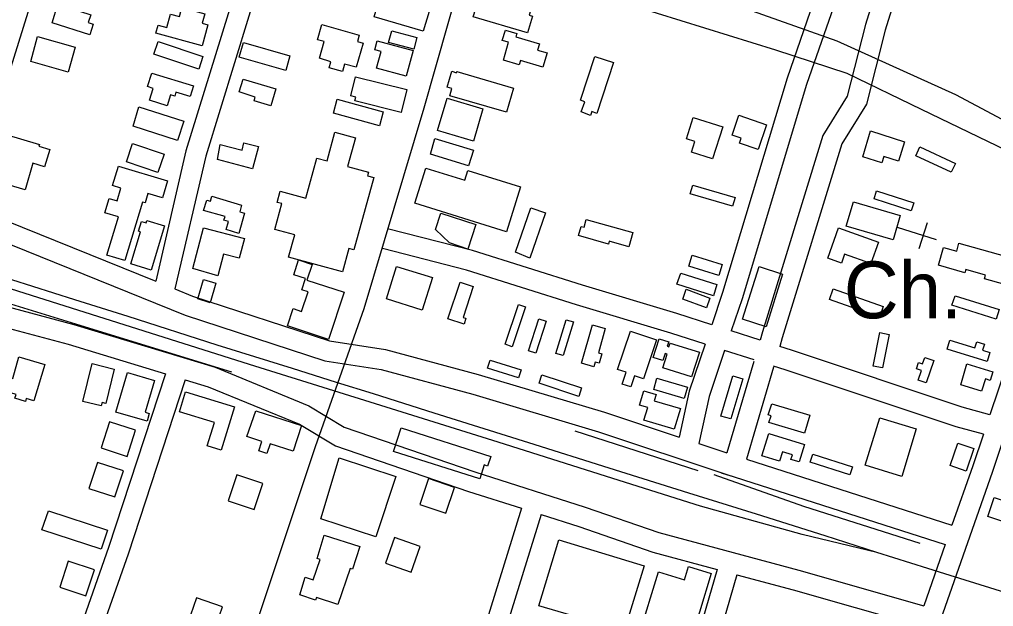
# Model space of a CAD drawing. Extents: x 3324125 to 3362000, y 600753 to 626151.
# Drawn here: x 3339347 to 3340770, y 607022 to 607880 of the extents above; entities that cross this region are included whole.
import ezdxf

# ---------------------------------------------------------------- set-up
doc = ezdxf.new("R2010")
doc.units = 0
for name, color, linetype in [('V-BLDG-OTLN', 7, 'Continuous'), ('V-RAIL-TRAK', 7, 'Continuous'), ('V-ROAD-CNTR', 7, 'Continuous'), ('V-SITE-OTLN', 7, 'Continuous'), ('V-SITE-OTLN-IDEN', 7, 'Continuous'), ('V-TOPO-SHOR', 7, 'Continuous')]:
    doc.layers.add(name, color=color, linetype=linetype)

msp = doc.modelspace()

# ---------------------------------------------------------------- linework, layer by layer
at = {"layer": 'V-BLDG-OTLN'}
for points in [[(3340021.5, 607919.4), (3340095.5, 607897.4), (3340092.1, 607886), (3340096.8, 607884.5), (3340089.5, 607860.1), (3340010.3, 607883.7)], [(3339395.3, 607874.7), (3339403.2, 607901.9), (3339451.6, 607886.6), (3339447.9, 607875.1), (3339455.2, 607872.8), (3339450.3, 607857.3)], [(3339874, 607912.4), (3339945.6, 607891.4), (3339937.1, 607862.7), (3339865.6, 607883.8)], [(3339546.5, 607859.7), (3339549.9, 607871.2), (3339562.6, 607867.8), (3339568, 607887.5), (3339580.9, 607884), (3339584.6, 607897.3), (3339618.1, 607888.1), (3339614.4, 607874.4), (3339622.6, 607872.1), (3339614.2, 607841.3)], [(3339785.4, 607823.1), (3339792.3, 607847.5), (3339782.6, 607850.2), (3339788.8, 607872.5), (3339843.8, 607857), (3339841.1, 607847.4), (3339849.2, 607845.2), (3339839.2, 607809.9), (3339822.3, 607814.6), (3339819.3, 607803.8), (3339799.9, 607809.2), (3339802.3, 607817.9)], [(3339886.6, 607846.3), (3339891.4, 607863.1), (3339927.9, 607853.5), (3339923.4, 607836.5)], [(3340054.5, 607820.4), (3340061.6, 607846.5), (3340052.6, 607849.1), (3340057.1, 607864.3), (3340073.8, 607859.3), (3340072.3, 607854.5), (3340106.8, 607844.1), (3340104.1, 607835.1), (3340118.2, 607830.9), (3340111.9, 607809.9), (3340079.3, 607819.6), (3340077.5, 607813.6)], [(3339364.1, 607818.2), (3339373.9, 607854.9), (3339428.9, 607839.2), (3339418.4, 607802.6)], [(3339609.2, 607807.1), (3339543.6, 607829.1), (3339549.8, 607847.4), (3339615, 607825.5)], [(3339742.5, 607826.5), (3339736.3, 607805.1), (3339668.3, 607824.8), (3339674.5, 607846.2)], [(3339869, 607808.4), (3339875.6, 607833.1), (3339866.4, 607835.6), (3339869.9, 607848.7), (3339922.5, 607834.6), (3339912.4, 607796.8)], [(3340190.9, 607742.1), (3340183.6, 607745.3), (3340181.3, 607739.5), (3340167.9, 607745), (3340173.3, 607759.2), (3340166.7, 607761.8), (3340187.9, 607825.6), (3340215.1, 607816.8)], [(3340069.2, 607779.3), (3340058.9, 607744.3), (3339976.1, 607768.4), (3339979.1, 607778.7), (3339972.1, 607780.8), (3339978.8, 607804), (3339985.7, 607802), (3339986.1, 607803.5)], [(3339540.8, 607801.1), (3339601.6, 607782.6), (3339596.9, 607767.1), (3339575.7, 607773.5), (3339574.1, 607767.9), (3339568, 607769.7), (3339563.2, 607753.7), (3339537.3, 607761.6), (3339542.6, 607779.1), (3339534.4, 607781.6)], [(3339674.1, 607792.3), (3339721.8, 607778.2), (3339714.6, 607753.7), (3339690.2, 607760.9), (3339691.8, 607766.2), (3339668.2, 607773.8)], [(3339904.7, 607743.9), (3339837.1, 607760.7), (3339838.5, 607766.3), (3339831.2, 607768.1), (3339838.1, 607796), (3339913, 607777.5)], [(3339805.9, 607742.8), (3339811.5, 607763.2), (3339878.7, 607744.7), (3339873.1, 607724.3)], [(3339957.9, 607717.5), (3339972.1, 607764.8), (3340024.4, 607749.3), (3340010.4, 607702)], [(3339521.6, 607752.2), (3339587.2, 607731.3), (3339578.1, 607702.9), (3339513.2, 607723.7)], [(3340374.6, 607723), (3340359.5, 607675.9), (3340329, 607685.6), (3340334.1, 607701.4), (3340321.6, 607705.4), (3340331.6, 607736.7)], [(3340438.7, 607726), (3340426.4, 607689.6), (3340399.1, 607698.8), (3340401.6, 607706.2), (3340388.4, 607710.7), (3340398.2, 607739.7)], [(3340579.5, 607679), (3340590.4, 607716.8), (3340640.3, 607700.9), (3340631.4, 607672.8), (3340609.8, 607679.6), (3340606.9, 607670.4)], [(3339355.8, 607630.6), (3339322.6, 607640.7), (3339321.6, 607637.4), (3339304.8, 607642.5), (3339326, 607712.2), (3339376.4, 607696.8), (3339375.7, 607694.6), (3339391.8, 607689.7), (3339384.1, 607664.6), (3339366.8, 607669.9)], [(3339740.5, 607532.5), (3339749.4, 607565), (3339720.2, 607573), (3339730.5, 607610.6), (3339723.7, 607612.5), (3339728.2, 607628.8), (3339765.7, 607618.5), (3339781.8, 607677.3), (3339796.7, 607673.2), (3339808.2, 607715), (3339838.1, 607706.8), (3339826.7, 607665.1), (3339857.2, 607656.7), (3339855.7, 607651.4), (3339865, 607648.8), (3339836, 607543.1), (3339828.4, 607545.2), (3339819, 607511)], [(3339947.8, 607682.9), (3339954.3, 607705.8), (3340010.5, 607688.7), (3340003.5, 607665.9)], [(3339503.5, 607671.7), (3339512.6, 607698.6), (3339558.6, 607683), (3339549.5, 607656.2)], [(3339636.5, 607674.9), (3339640.6, 607697.2), (3339672.5, 607688.9), (3339675.3, 607699.5), (3339696.3, 607694), (3339687.8, 607661.6)], [(3340656.7, 607680.7), (3340662.6, 607693.8), (3340714.6, 607669.4), (3340708.5, 607656.4)], [(3339491.9, 607665.5), (3339563.7, 607643.8), (3339556.2, 607619), (3339535, 607625.4), (3339530.9, 607611.8), (3339527.2, 607612.9), (3339501.4, 607527.4), (3339474.9, 607535.4), (3339491.8, 607591.5), (3339472, 607597.4), (3339478.3, 607618.1), (3339490, 607614.6), (3339495.6, 607633.2), (3339483.4, 607636.9)], [(3339925, 607611.1), (3339941.2, 607662.5), (3339997.9, 607644.9), (3340002.3, 607659.1), (3340079.1, 607635.2), (3340058.7, 607569.5)], [(3340327.1, 607624.9), (3340330.9, 607637.4), (3340392.7, 607619.4), (3340389.1, 607606.8)], [(3339649.1, 607572.6), (3339652.8, 607584.7), (3339646.1, 607586.6), (3339647.6, 607591.6), (3339616.4, 607600.7), (3339620.9, 607615.9), (3339626.5, 607614.3), (3339628.5, 607621.3), (3339671.9, 607608.6), (3339669, 607598.6), (3339676.2, 607596.5), (3339667.6, 607567.2)], [(3340595.7, 607617.5), (3340599.3, 607629.3), (3340653.7, 607611.9), (3340650, 607600.2)], [(3340071.8, 607539.6), (3340094.2, 607604.5), (3340115.7, 607597), (3340092.9, 607531.1)], [(3340555, 607577.8), (3340565.9, 607613.2), (3340633.8, 607593.5), (3340623.5, 607557.9)], [(3340013.9, 607580), (3340002.3, 607544.3), (3339975.3, 607553.1), (3339955.2, 607572.8), (3339962.9, 607596.5)], [(3339510.1, 607522.4), (3339524.3, 607569.3), (3339521.4, 607570.2), (3339525.8, 607584.7), (3339532.4, 607582.7), (3339533.4, 607586), (3339559.4, 607578.1), (3339539.6, 607513.4)], [(3339600.8, 607515.7), (3339616.3, 607575.1), (3339676, 607559.5), (3339668.5, 607530.8), (3339645.6, 607536.8), (3339637.3, 607505.1)], [(3340175.1, 607587.5), (3340243.2, 607568.4), (3340237.4, 607547.6), (3340209, 607555.6), (3340207.9, 607551.6), (3340164.1, 607563.9), (3340167.8, 607577.4), (3340172.5, 607576.1)], [(3340543.7, 607575.2), (3340602, 607554.5), (3340590.9, 607523.2), (3340552.6, 607536.8), (3340548, 607523.8), (3340528.4, 607530.7)], [(3340689.9, 607520.5), (3340697.1, 607546.4), (3340716.5, 607541), (3340719.8, 607552.6), (3340798, 607530.7), (3340796.4, 607525.1), (3340801, 607523.8), (3340793.6, 607497.4), (3340788.5, 607498.8), (3340786.7, 607492.4), (3340757.2, 607500.7), (3340758.7, 607506.2), (3340729.8, 607514.3), (3340728.5, 607509.7)], [(3340325.2, 607519.3), (3340329.9, 607535.4), (3340373.9, 607521.5), (3340368.9, 607505.5)], [(3339739, 607431.9), (3339747.3, 607457.2), (3339759.4, 607453.2), (3339768.9, 607481.7), (3339759.8, 607484.7), (3339765.2, 607501.1), (3339748, 607506.8), (3339755.1, 607528.4), (3339774.7, 607521.9), (3339767.1, 607499), (3339821.6, 607481), (3339798.8, 607412.1)], [(3339883.6, 607471.3), (3339898.1, 607518.9), (3339950.5, 607502.6), (3339935.7, 607455.1)], [(3340403.4, 607441.6), (3340427.7, 607518.5), (3340462.2, 607507.6), (3340437.9, 607430.7)], [(3340307.8, 607492.7), (3340313.7, 607509.2), (3340366.3, 607492.4), (3340361, 607475.7)], [(3339608.1, 607471.7), (3339616.4, 607499.7), (3339634.2, 607494.5), (3339625.7, 607465.6)], [(3339990.9, 607495.6), (3340009.9, 607489.4), (3339995.3, 607444.4), (3339999.6, 607443), (3339996.9, 607434.7), (3339973.2, 607442.4)], [(3340316.5, 607471.2), (3340321.4, 607485.4), (3340356, 607472.7), (3340350.8, 607458.5)], [(3340530.5, 607470.6), (3340535.9, 607486), (3340609.1, 607460.3), (3340603.7, 607444.9)], [(3340709.6, 607462.3), (3340714.1, 607475.9), (3340778.4, 607455.7), (3340774.1, 607442)], [(3340057, 607405.1), (3340076.2, 607463), (3340086.4, 607459.6), (3340067.1, 607401.5)], [(3340090.9, 607395.7), (3340106.1, 607442.3), (3340116.8, 607438.8), (3340101.6, 607392.1)], [(3340131, 607391.8), (3340145.8, 607441), (3340156.5, 607437.7), (3340141.7, 607388.5)], [(3340168.5, 607377.3), (3340184.4, 607433.4), (3340203.1, 607428.2), (3340193, 607392.7), (3340198.1, 607391.3), (3340194.1, 607377.3), (3340188.3, 607379), (3340186.4, 607372.2)], [(3340277.8, 607411.8), (3340258.9, 607354.6), (3340245.6, 607359), (3340240.2, 607342.8), (3340227.7, 607346.9), (3340233.5, 607364.1), (3340221.1, 607368.2), (3340239.8, 607424.4)], [(3340594.4, 607373.1), (3340604.1, 607422.1), (3340617.8, 607419.4), (3340608.2, 607370.4)], [(3340340.5, 607393.4), (3340329.2, 607357.6), (3340287.3, 607370.5), (3340293.4, 607390.6), (3340290.6, 607391.4), (3340287.4, 607381.2), (3340273.2, 607385.7), (3340281.9, 607413.2), (3340295.8, 607408.8), (3340293.7, 607402.1), (3340296, 607401.4), (3340297.7, 607406.9)], [(3340760.8, 607379.7), (3340702.5, 607397.8), (3340706.6, 607411.1), (3340743.2, 607399.7), (3340745.9, 607408.4), (3340757, 607405), (3340754.4, 607396.5), (3340764.9, 607393.2)], [(3339346.4, 607386.8), (3339384.3, 607375.3), (3339368.2, 607322.6), (3339357.3, 607325.9), (3339355.9, 607321.4), (3339340.6, 607326.1), (3339342.4, 607331.6), (3339320.6, 607338.3), (3339326.7, 607358.5), (3339337.6, 607355.2)], [(3339453.5, 607376.9), (3339485.9, 607368.9), (3339473.6, 607318.7), (3339468.1, 607320), (3339466.9, 607314.9), (3339439.8, 607321.5)], [(3340030.9, 607370.1), (3340035, 607381.7), (3340080.1, 607367.7), (3340076.5, 607356)], [(3340672, 607348.6), (3340660.4, 607352.6), (3340665.2, 607366.7), (3340657.6, 607369.3), (3340660.7, 607378.3), (3340666.7, 607376.3), (3340670, 607385.8), (3340683.2, 607381.3)], [(3340722.3, 607345.8), (3340731.5, 607376.6), (3340769.4, 607365), (3340765.5, 607352.3), (3340758.4, 607354.4), (3340752.9, 607336.4)], [(3339544.6, 607352.3), (3339530.8, 607305.7), (3339537, 607303.8), (3339533.7, 607292.5), (3339488.2, 607305.9), (3339505.3, 607363.9)], [(3340106.7, 607348), (3340110.3, 607360.5), (3340168.4, 607341.2), (3340164.3, 607328.8)], [(3340274, 607339), (3340278.5, 607355.4), (3340323.3, 607342.3), (3340318.5, 607326)], [(3340371.7, 607300.2), (3340389.4, 607358.9), (3340404, 607354.5), (3340386.3, 607296.1)], [(3339589.7, 607335.7), (3339661.5, 607313.6), (3339642.1, 607250.5), (3339621.6, 607256.8), (3339632.1, 607290.9), (3339581.2, 607306.5)], [(3340259.6, 607294.1), (3340265.4, 607312.5), (3340253, 607316.2), (3340259.4, 607337.2), (3340277.2, 607331.8), (3340274.4, 607322.6), (3340312.8, 607311), (3340303.7, 607280.8)], [(3340446.3, 607317.9), (3340501.7, 607301.6), (3340494, 607275.4), (3340442.2, 607290.6), (3340445.2, 607300.7), (3340441.2, 607301.8)], [(3339692.5, 607307.8), (3339759.2, 607286.5), (3339747.2, 607249), (3339713.4, 607259.8), (3339708.8, 607245.4), (3339697.1, 607249.1), (3339701.6, 607263.2), (3339679.5, 607270.3)], [(3339504.5, 607241.3), (3339516.9, 607279.3), (3339478.9, 607291.8), (3339466.5, 607253.7)], [(3340582.7, 607228.6), (3340604, 607297.8), (3340657.5, 607281.4), (3340636.1, 607211.9)], [(3339904.9, 607282.8), (3340035.7, 607241.2), (3340031.2, 607227.1), (3340026.3, 607228.7), (3340019.9, 607208.3), (3339893.8, 607248.4)], [(3340431.9, 607242.1), (3340441.8, 607274.5), (3340494, 607258.5), (3340486.2, 607233.3), (3340474.3, 607236.9), (3340476.4, 607243.6), (3340462.1, 607248), (3340457.8, 607234.1)], [(3340706.9, 607227.8), (3340718.1, 607260.6), (3340741.5, 607252.6), (3340730.2, 607219.4)], [(3339486.8, 607182), (3339499.2, 607220), (3339461.2, 607232.4), (3339448.7, 607194.4)], [(3339787.5, 607150.1), (3339814.4, 607239.1), (3339897.2, 607211.8), (3339868, 607123.5)], [(3340502.6, 607232.8), (3340506.5, 607244.5), (3340564.3, 607226.1), (3340560.5, 607214.3)], [(3339690, 607163.6), (3339702.8, 607201.5), (3339664.9, 607214.3), (3339652.1, 607176.4)], [(3339982.8, 607195.9), (3339944.9, 607208.7), (3339932.1, 607170.8), (3339970, 607158)], [(3340887.3, 607142.3), (3340878.3, 607114.6), (3340842.5, 607126.6), (3340844.2, 607131.5), (3340820.8, 607139.3), (3340819.1, 607134.3), (3340761.9, 607153.4), (3340771.2, 607181.1)], [(3339389.7, 607161.6), (3339475.7, 607133.5), (3339466.6, 607105.7), (3339379.8, 607134)], [(3339756.9, 607038.8), (3339764.8, 607064.6), (3339776.5, 607060.7), (3339786.6, 607090.6), (3339782.1, 607092.1), (3339792.4, 607126.1), (3339844.3, 607109.6), (3339833.9, 607076.4), (3339830.3, 607077.6), (3339812.4, 607024.6), (3339781.4, 607035), (3339780, 607031.1)], [(3339932.8, 607109.6), (3339895.1, 607122.8), (3339881.8, 607085.1), (3339919.6, 607071.9)], [(3340106, 607022.9), (3340135.2, 607119.2), (3340259.8, 607081.5), (3340230.9, 606986.2)], [(3339444.3, 607037.5), (3339456.7, 607075.5), (3339418.7, 607087.9), (3339406.2, 607049.9)], [(3340252.3, 606978.8), (3340280.9, 607072.4), (3340318.8, 607060.8), (3340324.7, 607080.1), (3340358, 607069.9), (3340323.6, 606957.2)], [(3339630.9, 606983.5), (3339643.7, 607021.4), (3339605.8, 607034.3), (3339593, 606996.4)]]:
    msp.add_lwpolyline(points, close=True, dxfattribs=at)
at = {"layer": 'V-RAIL-TRAK'}
for points in [[(3340342.3, 607168.5), (3340214.1, 607208.9), (3340046.4, 607261.8), (3339867.5, 607318.1), (3339806.6, 607337.1), (3339683.6, 607375.3), (3339452.7, 607448.4), (3339256.9, 607510.3), (3339233.1, 607517.7), (3339114.4, 607556), (3338941.5, 607610.2), (3338770.8, 607663.9), (3338616.1, 607712.1), (3338384, 607785.4), (3338129, 607865.5)], [(3339506.3, 607445.6), (3339428.3, 607470.1), (3339274.1, 607518.6), (3339236.7, 607530.7), (3339161.8, 607554.3), (3339037, 607593.5), (3338878, 607643.8), (3338754.5, 607682.4), (3338609, 607728.9), (3338482, 607768.4), (3338335.2, 607815.3), (3338181, 607863.9)], [(3340816.5, 607032.9), (3340699, 607069.6), (3340599.6, 607100.7), (3340524.1, 607124.9), (3340424, 607156.7), (3340325.2, 607187.7), (3340208.7, 607224), (3340091.3, 607261.2), (3339953.1, 607304.3), (3339864.7, 607332.5), (3339810.5, 607349.4), (3339746.4, 607369.6), (3339636, 607403.9), (3339506.3, 607445.6)], [(3340599.6, 607100.7), (3340490.5, 607127.3), (3340342.3, 607168.5)]]:
    msp.add_lwpolyline(points, dxfattribs=at)
at = {"layer": 'V-ROAD-CNTR'}
for points in [[(3339883.1, 608748.6), (3339846.5, 608600.3), (3339828.2, 608538.2), (3339723.8, 608153.1), (3339695.5, 608029), (3339590.4, 607687.6), (3339546.3, 607497.3)], [(3339912.3, 608741.4), (3339875.5, 608592.5), (3339857.1, 608530), (3339752.9, 608145.9), (3339724.5, 608021.3), (3339619.4, 607679.8), (3339574.4, 607486)], [(3339271.1, 607605), (3339277.6, 607627.6), (3339428, 608110), (3339471.4, 608240.6), (3339580.5, 608609.5), (3339593.8, 608640.1)], [(3340880.6, 608635), (3340915.1, 608606.2), (3341166.1, 608521.9), (3340907.9, 607736), (3340856.4, 607573.3), (3340765.1, 607302.1)], [(3340836.6, 608614.5), (3340830.2, 608575.2), (3340725.1, 608227), (3340612.2, 607864.2), (3340584.7, 607755.8), (3340548.5, 607697.8), (3340461.7, 607414.7), (3340457.9, 607402)], [(3339432.1, 606157.1), (3339565.6, 606591.7), (3339595.2, 606701.5), (3339779.9, 607255.8), (3339850.8, 607457.2), (3339938.7, 607750.4), (3339991.4, 607937.6), (3340033.3, 608065.6), (3340109.3, 608306.5), (3340151.5, 608473.1)], [(3338095.1, 608382.4), (3338259.1, 608370.6), (3338551.7, 608360.9), (3338678.9, 608355.4), (3338759.9, 608349.8), (3338867.9, 608336.9), (3338938.4, 608324.4), (3339016.8, 608313.1), (3339101, 608289.9), (3339704.4, 608109), (3340246.4, 607951.2), (3340394.5, 607900.5), (3340541.5, 607848.4), (3340714.9, 607769.9), (3340880.1, 607681.8)], [(3338030.8, 608297.2), (3338260.6, 608280.3), (3338440.8, 608273.8), (3338606.7, 608268.3), (3338780.2, 608265.1), (3338943.4, 608261), (3339024.4, 608253.5), (3339134, 608234.5), (3339262.6, 608211.2), (3339404.8, 608161.6), (3340039.2, 607964.4), (3340279.1, 607888.9), (3340451.7, 607835.6), (3340556, 607801.3), (3340664.6, 607748.6), (3340802.7, 607681.7)], [(3340608.8, 608214.7), (3340594.2, 608182.3), (3340511.7, 607918.6), (3340468.7, 607793.9), (3340374.4, 607480.6), (3340358.6, 607433.7)], [(3340637.7, 608205.8), (3340622.2, 608171.6), (3340540.2, 607909.2), (3340497.2, 607784.6), (3340403, 607471.5), (3340387.2, 607424.6)], [(3340682.8, 608191.8), (3340583.3, 607872.3), (3340556.7, 607767.7), (3340521, 607710.4), (3340433, 607423.4), (3340429.4, 607411.1)], [(3339271.1, 607605), (3339302.8, 607595.8), (3339546.3, 607497.3)], [(3339262.7, 607576.1), (3339293, 607567.4), (3339589.6, 607447.5), (3339793.3, 607380.8), (3339875.7, 607368.2), (3340009.4, 607332), (3340193, 607277.2), (3340379.2, 607215.1), (3340699.7, 607112.5)], [(3340358.6, 607433.7), (3340307.8, 607450), (3340169.9, 607491.4), (3340008.9, 607542.3), (3339885.2, 607574)], [(3340349, 607405.3), (3340298.9, 607421.3), (3340161.1, 607462.7), (3340000.6, 607513.4), (3339877.8, 607544.9)], [(3339236.4, 607485), (3339426.9, 607434), (3339633.2, 607371.4), (3339769.9, 607315), (3339821.5, 607283.8), (3340012.7, 607218.6), (3340173.9, 607167.2), (3340281.3, 607129.8), (3340485.7, 607075.1), (3340668.4, 607023)], [(3339574.4, 607486), (3339599.9, 607475.6), (3339800.3, 607410.1), (3339881.9, 607397.6), (3340017.6, 607360.8), (3340202, 607305.8), (3340311, 607269.4)], [(3339228.1, 607456.1), (3339418.7, 607405.1), (3339560.7, 607362)], [(3340429.4, 607411.1), (3340387.2, 607424.6)], [(3340349, 607405.3), (3340325.7, 607336.6), (3340311, 607269.4)], [(3340377.5, 607396.2), (3340354.7, 607328.6), (3340339.6, 607259.9)], [(3340420.4, 607382.5), (3340377.5, 607396.2)], [(3340765.1, 607302.1), (3340724.4, 607313.2), (3340475.2, 607396.4), (3340457.9, 607402)], [(3340420.1, 607379.9), (3340380.7, 607246.2)], [(3339560.7, 607362), (3339477.5, 607107.9), (3339355.5, 606760.6), (3339348.3, 606736.8)], [(3340449, 607371.7), (3340409.3, 607237)], [(3340755.5, 607273.7), (3340715.7, 607284.5), (3340465.9, 607367.9), (3340449, 607373.3)], [(3339589.5, 607353.3), (3339505.9, 607098.2), (3339384.1, 606751.3), (3339376.5, 606726.2)], [(3339589.5, 607353.3), (3339623.1, 607343.1), (3339756.4, 607288.1), (3339808.8, 607256.5), (3340003.3, 607190.1), (3340080.7, 607165.5)], [(3340784.5, 607265.8), (3340768.3, 607217.6), (3340683.2, 606974.6), (3340572.3, 606625.3), (3340477.1, 606345), (3340245.4, 606418.3), (3340202.5, 606434.2)], [(3340755.5, 607273.7), (3340740, 607227.4), (3340709.6, 607140.8)], [(3340339.6, 607259.9), (3340380.7, 607246.2)], [(3340409.3, 607237), (3340709.6, 607140.8)], [(3340372.2, 607217.3), (3340386.7, 607212.7)], [(3340080.7, 607165.5), (3339958.3, 606770.6), (3339901.9, 606588), (3339890.1, 606562)], [(3340109.3, 607156.3), (3339987, 606761.7), (3339930, 606577.3), (3339919.4, 606553.8)], [(3340109.3, 607156.3), (3340164.4, 607138.8), (3340272.5, 607101.1), (3340366.5, 607075.9)], [(3340699.7, 607112.5), (3340668.4, 607023)], [(3340366.5, 607075.9), (3340275.9, 606764.1), (3340188.7, 606491.2), (3340183.2, 606473.4)], [(3340395.5, 607068.1), (3340304.6, 606755.4), (3340217.3, 606482.2), (3340211.3, 606462.9)], [(3340395.5, 607068.1), (3340477.7, 607046.2), (3340658.5, 606994.6)]]:
    msp.add_lwpolyline(points, dxfattribs=at)
at = {"layer": 'V-SITE-OTLN'}
for p, q in [((3340629.5, 607576), (3340686.7, 607558)), ((3340661.6, 607544.9), (3340673.6, 607583))]:
    msp.add_line(p, q, dxfattribs=at)
at = {"layer": 'V-TOPO-SHOR'}
for p, q in [((3339253.7, 607488.6), (3339657.2, 607365)), ((3340338.9, 607220.2), (3340159.3, 607278.1)), ((3340493.3, 607168), (3340362, 607214.4)), ((3340663.3, 607114), (3340493.3, 607168))]:
    msp.add_line(p, q, dxfattribs=at)

# ---------------------------------------------------------------- texts
at = {"layer": 'V-SITE-OTLN-IDEN'}
msp.add_text('Ch.', height=83, dxfattribs=at).set_placement((3340551.6, 607443))

doc.saveas('drawing.dxf')
